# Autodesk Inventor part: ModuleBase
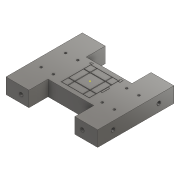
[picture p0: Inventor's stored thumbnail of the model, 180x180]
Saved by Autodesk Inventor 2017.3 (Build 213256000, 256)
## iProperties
Part Number: ModuleBase
Material: ステンレス鋼
Document SubType Name: Modeling
Designer: kyushu-hep
Density: 8 g/cm^3
Appearance: 半つや出し
Mass: 96.9479 g
Surface Area: 172.882 cm^2
Volume: 104.245 cm^3
Author: kyushu-hep
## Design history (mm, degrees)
sketch "スケッチ1"
  geometry: L1 (-60, 50)-(60, 50); L2 (60, 50)-(60, -50); L3 (60, -50)-(-60, -50); L4 (-60, -50)-(-60, 50); 1 further point
  constraints: 8 end point, 2 parallel, 1 horizontal, 1 perpendicular
  dimensions: "d0" = 120 distance of L2.end L3.end; "d1" = 100 distance of L1.end L2.end; "d22" = 50 distance from line of point (0, 0) L3; "d23" = 60 distance from line of L2 point (0, 0)
extrude "押し出し1" new body sketch "スケッチ1" distance "d2" = 20; taper "d3" = 0 deg
sketch "スケッチ4"
  geometry: L1 (17.855, 22.225)-(17.855, 20.225); L2 (17.855, 20.225)-(19.055, 20.225); L3 (19.055, 20.225)-(19.055, 18.225); L4 (19.055, 18.225)-(21.055, 18.225); L5 (21.055, 18.225)-(21.055, 22.225); L6 (21.055, 22.225)-(17.855, 22.225); L7 (21.055, 5)-(21.055, -5); L8 (21.055, -5)-(19.055, -5); L9 (19.055, -5)-(19.055, 5); L10 (19.055, 5)-(21.055, 5); L11 (-60, -50)-(60, -50) reference; L12 (-60, 50)-(-60, -50) reference; L13 (-21.055, 22.225)-(-17.855, 22.225); L14 (-17.855, 22.225)-(-17.855, 20.225); L15 (-17.855, 20.225)-(-21.055, 20.225); L16 (-21.055, 20.225)-(-21.055, 22.225); 1 further point
  constraints: 28 end point, 8 perpendicular, 4 point on line, 2 parallel, 1 collinear, 1 horizontal, 1 vertical
  dimensions: "d12" = 2 distance of L1.start L1.end; "d13" = 1.2 distance of L1.end L2.end; "d14" = 2 distance of L2.end L3.end; "d15" = 2 distance of L3.end L4.end; "d16" = 10 distance of L7.start L7.end; "d24" = 19.055 distance from line of L9 point (0, 0); "d25" = 22.225 distance from line of point (0, 0) L6; "d28" = 17.855 distance from line of point (0, 0) L14
extrude "押し出し4" join sketch "スケッチ4" distance "d29" = 0.3; taper "d30" = 0 deg
sketch "スケッチ6"
  geometry: L1 (20, 20)-(-20, 20); L2 (-20, 20)-(-20, -20); L3 (-20, -20)-(20, -20); L4 (20, -20)-(20, 20); L5 (20, 20)-(-20, -20); L6 (-20, 20)-(20, -20); C1 r 1.5 at (-16, -16); C2 r 1.5 at (-16, 16); C3 r 1.5 at (16, -16); C4 r 1.5 at (16, 16); 1 further point
  constraints: 12 end point, 4 centre point, 2 horizontal, 2 midpoint, 2 parallel, 1 perpendicular, 1 vertical, 6 other
  dimensions: "d41" = 3 diameter of C1; "d42" = 16 horizontal distance of point (0, 0) C1.centre; "d43" = 16 horizontal distance of point (0, 0) C1.centre; "d44" = 40 distance of L3.end L2.end; "d45" = 40 distance of L2.end L1.end; "d48" = 32 distance of C1.centre C2.centre; "d51" = 32 distance of C1.centre C3.centre
sketch "スケッチ7"
  geometry: C1 r 0.5 at (-10, 10); C2 r 0.5 at (10, 10); C3 r 0.5 at (-10, -10); C4 r 0.5 at (10, -10); 1 further point
  constraints: 4 centre point
  dimensions: "d58" = 1 diameter of C1; "d59" = 10 horizontal distance of point (0, 0) C1.centre; "d60" = 10 horizontal distance of point (0, 0) C1.centre; "d61" = 1 diameter of C2; "d62" = 10 horizontal distance of point (0, 0) C2.centre; "d63" = 1 diameter of C3; "d64" = 10 horizontal distance of point (0, 0) C3.centre; "d65" = 1 diameter of C4
extrude "押し出し9" cut sketch "スケッチ7" distance "d66" = 10; taper "d67" = 0 deg
sketch "スケッチ9"
  geometry: L1 (18.5, -19.5)-(-18.5, -19.5); L2 (-18.5, -19.5)-(-18.5, 19.5); L3 (-18.5, 19.5)-(18.5, 19.5); L4 (18.5, 19.5)-(18.5, -19.5); L5 (18.5, -19.5)-(-18.5, 19.5); L6 (-18.5, -19.5)-(18.5, 19.5); L7 (-10.5, 10.5)-(-18, 10.5); L8 (-18, 10.5)-(-18, 19); L9 (-18, 19)-(-10.5, 19); L10 (-10.5, 19)-(-10.5, 10.5); L11 (-10.5, 10.5)-(-18, 19); L12 (-18, 10.5)-(-10.5, 19); L13 (18, 10.5)-(10.5, 10.5); L14 (10.5, 10.5)-(10.5, 19); L15 (10.5, 19)-(18, 19); L16 (18, 19)-(18, 10.5); L17 (-9.5, 19)-(9.5, 19); L18 (9.5, 19)-(9.5, 10.5); L19 (9.5, 10.5)-(-9.5, 10.5); L20 (-9.5, 10.5)-(-9.5, 19); L21 (-18, 9.5)-(-10.5, 9.5); L22 (-10.5, 9.5)-(-10.5, -9.5); L23 (-10.5, -9.5)-(-18, -9.5); L24 (-18, -9.5)-(-18, 9.5); L25 (-18, -10.5)-(-10.5, -10.5); L26 (-10.5, -10.5)-(-10.5, -19); L27 (-10.5, -19)-(-18, -19); L28 (-18, -19)-(-18, -10.5); L29 (-9.5, 9.5)-(9.5, 9.5); L30 (9.5, 9.5)-(9.5, -9.5); L31 (9.5, -9.5)-(-9.5, -9.5); L32 (-9.5, -9.5)-(-9.5, 9.5); L33 (10.5, 9.5)-(18, 9.5); L34 (18, 9.5)-(18, -9.5); L35 (18, -9.5)-(10.5, -9.5); L36 (10.5, -9.5)-(10.5, 9.5); L37 (-9.5, -10.5)-(9.5, -10.5); L38 (9.5, -10.5)-(9.5, -19); L39 (9.5, -19)-(-9.5, -19); L40 (-9.5, -19)-(-9.5, -10.5); L41 (10.5, -10.5)-(18, -10.5); L42 (18, -10.5)-(18, -19); L43 (18, -19)-(10.5, -19); L44 (10.5, -19)-(10.5, -10.5); 2 further points
  constraints: 88 end point, 20 parallel, 19 collinear, 10 horizontal, 10 perpendicular, 4 midpoint, 4 point on line
  dimensions: "d78" = 37 distance of L2.end L3.end; "d79" = 39 distance of L1.end L2.end; "d80" = 7.5 distance of L8.end L9.end; "d81" = 0.5 distance between parallel lines of L3 L9; "d82" = 0.5 distance between parallel lines of L2 L8; "d83" = 8.5 distance of L7.end L8.end; "d88" = 19 distance of L18.end L19.end; "d89" = 8.5 distance of L17.end L18.end; "d90" = 1 distance between parallel lines of L10 L20; "d92" = 19 distance of L21.end L22.end; "d93" = 1 distance between parallel lines of L21 L7; "d94" = 8.5 distance of L25.end L26.end; "d95" = 1 distance between parallel lines of L25 L23; "d96" = 8.5 distance of L13.end L14.end; "d97" = 1 distance between parallel lines of L14 L18
extrude "押し出し11" cut sketch "スケッチ9" distance "d98" = 1; taper "d99" = 0 deg
extrude "押し出し13" cut sketch "スケッチ6" distance "d102" = 10; taper "d103" = 0 deg
sketch "スケッチ10"
  geometry: 1 further point
sketch "スケッチ11"
  geometry: L1 (20, 20)-(-20, 20); L2 (-20, 20)-(-20, -20); L3 (-20, -20)-(20, -20); L4 (20, -20)-(20, 20); L5 (20, 20)-(-20, -20); L6 (-20, 20)-(20, -20); C1 r 1.5 at (-48, -16); C2 r 1.5 at (-48, 16); C3 r 1.5 at (-32, -16); C4 r 1.5 at (-32, 16); C5 r 1.5 at (-16, -16); C6 r 1.5 at (-16, 16); C7 r 1.5 at (0, -16); C8 r 1.5 at (0, 16); C9 r 1.5 at (16, -16); C10 r 1.5 at (16, 16); C11 r 1.5 at (32, -16); C12 r 1.5 at (32, 16); C13 r 1.5 at (48, -16); C14 r 1.5 at (48, 16); 3 further points
  constraints: 14 centre point, 12 end point, 2 horizontal, 2 midpoint, 2 parallel, 1 perpendicular, 1 vertical, 26 other
  dimensions: "d108" = 3 diameter of C1; "d109" = 48 horizontal distance of point (0, 0) C1.centre; "d110" = 16 vertical distance of point (0, 0) C1.centre; "d111" = 40 distance of L3.end L2.end; "d112" = 40 distance of L2.end L1.end; "d113" = 32 distance of C1.centre C2.centre; "d114" = 16 distance of C1.centre C3.centre
extrude "押し出し14" cut sketch "スケッチ11" distance "d115" = 10; taper "d116" = 0 deg
sketch "スケッチ12"
  geometry: C1 r 2.5 at (10, 80); C2 r 2.5 at (10, 20); 1 further point
  constraints: 2 centre point
  dimensions: "d117" = 5 diameter of C1; "d118" = 30 vertical distance of point (0, 50) C1.centre; "d119" = 10 horizontal distance of point (0, 50) C1.centre; "d120" = 5 diameter of C2; "d121" = 30 vertical distance of C2.centre point (0, 50); "d122" = 10 horizontal distance of point (0, 50) C2.centre
extrude "押し出し15" cut sketch "スケッチ12" distance "d123" = 10; taper "d124" = 0 deg
sketch "スケッチ13"
  geometry: C1 r 2.5 at (-10, 20); C2 r 2.5 at (-10, 80); 1 further point
  constraints: 2 centre point
  dimensions: "d125" = 5 diameter of C1; "d126" = 5 diameter of C2; "d127" = 10 horizontal distance of point (0, 50) C1.centre; "d128" = 30 vertical distance of point (0, 50) C1.centre; "d129" = 30 vertical distance of C2.centre point (0, 50); "d130" = 10 horizontal distance of C2.centre point (0, 50)
extrude "押し出し16" cut sketch "スケッチ13" distance "d131" = 10; taper "d132" = 0 deg
sketch "スケッチ14"
  geometry: C1 r 2.5 at (20, 10); C2 r 2.5 at (100, 10); 1 further point
  constraints: 2 centre point
  dimensions: "d133" = 5 diameter of C1; "d134" = 5 diameter of C2; "d135" = 10 vertical distance of point (60, 0) C1.centre; "d136" = 40 horizontal distance of point (60, 0) C1.centre; "d137" = 40 horizontal distance of C2.centre point (60, 0); "d138" = 10 vertical distance of point (60, 0) C2.centre
extrude "押し出し17" cut sketch "スケッチ14" distance "d139" = 10; taper "d140" = 0 deg
sketch "スケッチ15"
  geometry: C1 r 2.5 at (100, -10); C2 r 2.5 at (20, -10); 1 further point
  constraints: 2 centre point
  dimensions: "d141" = 5 diameter of C1; "d142" = 5 diameter of C2; "d143" = 40 horizontal distance of point (60, 0) C1.centre; "d144" = 40 horizontal distance of point (60, 0) C2.centre; "d145" = 10 vertical distance of point (60, 0) C1.centre; "d146" = 10 vertical distance of C2.centre point (60, 0)
extrude "押し出し18" cut sketch "スケッチ15" distance "d147" = 10; taper "d148" = 0 deg
feature "ねじ1" dims "d149" = 10, "d150" = 0
feature "ねじ2" dims "d151" = 10, "d152" = 0
feature "ねじ3" dims "d153" = 10, "d154" = 0
feature "ねじ4" dims "d155" = 10, "d156" = 0
feature "ねじ5" dims "d157" = 10, "d158" = 0
feature "ねじ6" dims "d159" = 10, "d160" = 0
feature "ねじ7" dims "d161" = 10, "d162" = 0
feature "ねじ8" dims "d163" = 10, "d164" = 0
sketch "スケッチ16"
  geometry: L1 (60, 50)-(-60, 50) reference; L2 (-30, 50)-(30, 50); L3 (30, 50)-(30, 25); L4 (30, 25)-(-30, 25); L5 (-30, 25)-(-30, 50); L6 (-30, -50)-(30, -50); L7 (30, -50)-(30, -25); L8 (30, -25)-(-30, -25); L9 (-30, -25)-(-30, -50); 1 further point
  constraints: 16 end point, 4 parallel, 2 horizontal, 2 perpendicular, 1 point on line
  dimensions: "d165" = 60 distance of L3.end L4.end; "d166" = 25 distance of L2.end L3.end; "d169" = 60 distance of L8.end L7.end; "d170" = 25 distance of L7.end L6.end; "d171" = 25 distance from line of L8 point (0, 0); "d172" = 30 distance from line of point (0, 0) L9; "d173" = 30 distance from line of L5 point (0, 0)
extrude "押し出し20" cut sketch "スケッチ16" distance "d174" = 20; taper "d175" = 0 deg
node "ソリッド1"
